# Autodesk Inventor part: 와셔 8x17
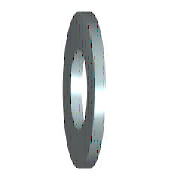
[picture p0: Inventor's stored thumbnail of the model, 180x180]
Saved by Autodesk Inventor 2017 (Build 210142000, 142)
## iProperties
Created: 2012-02
Part Number: 와셔 8x17
Material: 강철, 연강
Description: 평면 와셔
Document SubType Name: Modeling
Standard: KS B 1326
Designer: mduedu
Standards Organization: KS
Language: ko-KR
Size Designation: 8x17
Categories: <MemberInstance><Categories><Category DisplayName="조임쇠" InternalName="e4da775c-781d-43d5-af7c-5136215cf5a6" Mnemonic="FSTN"><Category DisplayName="와셔" InternalN
Density: 7.85 g/cm^3
Appearance: 파란색 - 벽 페인트 - 광택
Mass: 2.05184 g
Surface Area: 4.57416 cm^2
Volume: 0.261381 cm^3
IsCustomPart: 1
Author: mduedu
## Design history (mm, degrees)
sketch "스케치"
  geometry: C1 r 8.5 at (0, 0); C2 r 4.5 at (0, 0); 1 further point
  constraints: 2 centre point, 2 coincident
  dimensions: "d0" = 9 diameter of C2 (= SD1); "d1" = 17 diameter of C1 (= SD2)
extrude "본체" new body sketch "스케치" distance "d2" = 1.6 (= SD); taper "d3" = 0 deg
workaxis "Work Axis1"
workplane "Work Plane1"
body "Solid1"
other parameters: "SD1" = 9 [user parameter; used in 1 equation term], "SD2" = 17 [user parameter; used in 1 equation term], "SD" = 1.6 [user parameter; used in 1 equation term], "d4" = 0, "d5" = 0, "d6" = 0, "d7" = 0, "NND" = 8 [user parameter]
